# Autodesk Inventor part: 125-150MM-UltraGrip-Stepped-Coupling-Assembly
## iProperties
Created: 2012-05
Part Number: 125-150MM-UltraGrip-Stepped-Coupling-Assembly
Document SubType Name: Modeling
Designer: D Cole
Density: 1 g/cm^3
Author: D Cole
